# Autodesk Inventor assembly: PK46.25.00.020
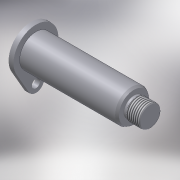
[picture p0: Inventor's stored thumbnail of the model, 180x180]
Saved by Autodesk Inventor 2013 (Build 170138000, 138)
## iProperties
Created: 2005-05
Part Number: PK46.25.00.020
Document SubType Name: Assembly
Designer: PVitaliy
Manufacturer: Standard
Standards Organization: Custom
Author: PVitaliy
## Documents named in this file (3)
- C:\Product Design Suite 2013 Test Drive\Dynamic Simulation\Workspace\Assy, Chassis, Front\PK46.25.00.020.iam
- C:\Product Design Suite 2013 Test Drive\Dynamic Simulation\Workspace\Assy, Chassis, Front\PK46.25.00.003.ipt
- C:\Product Design Suite 2013 Test Drive\Dynamic Simulation\Workspace\Assy, Chassis, Front\PK46.25.00.002.ipt
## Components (2 placed, 2 different names)
1. PK46.25.00.003:1 — Вставка:1
2. PK46.25.00.002:1 — Вставка:1, Совмещение:1
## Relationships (2: Insert 1, Mate 1)
- Вставка:1 [Insert]: PK46.25.00.003:1 ↔ PK46.25.00.002:1
- Совмещение:1 [Mate]: PK46.25.00.002:1
